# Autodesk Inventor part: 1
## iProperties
Created: 2012-03
Part Number: 1
Document SubType Name: Modeling
Designer: Administrator
Density: 7.85 g/cm^3
Material: Steel
Mass: 96.7784 g
Surface Area: 83.7444 cm^2
Volume: 12.3285 cm^3
Translation Standard: STEP AP203
FileName: //expscmdclustefs.cadenas.external/client_exchange/iodir/jobs/output/wkb42693463_no0/STEP/229_9001_2_03.stp
PostProcessor: Build: 236a, Release: 2009 RTM - Date: Fri 02/22/2008
Sent Units: MM
Uncertainty: 1.0000000000000002e-06
Author: Administrator
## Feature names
1. Base1
